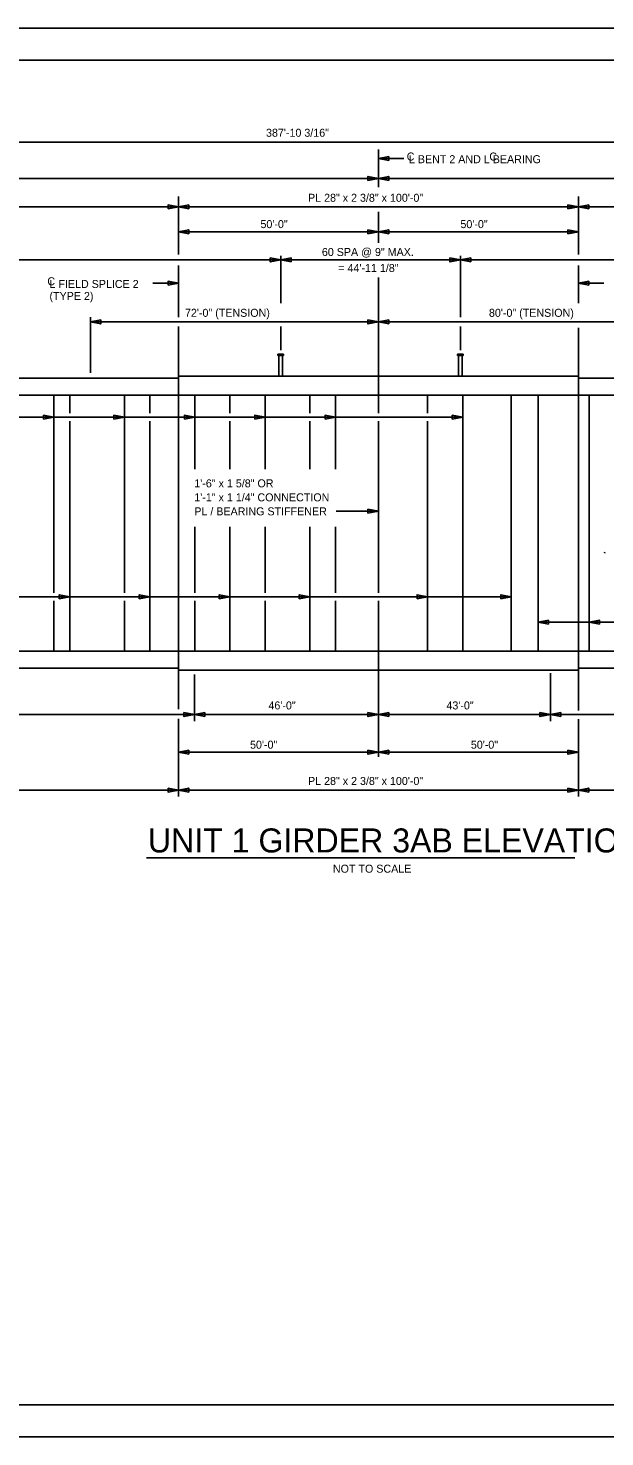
# Model space of a CAD drawing. Extents: x -305 to -161, y -187 to -99.
# Drawn here: x -251.9 to -215.9, y -187.5 to -99.5 of the extents above; entities that cross this region are included whole.
import ezdxf

# ---------------------------------------------------------------- set-up
doc = ezdxf.new("R2010")
doc.units = 0
for name, color, linetype in [('BR_AUTO DIMENSION', 7, 'Continuous'), ('BR_BORDER LINES', 7, 'Continuous'), ('BR_CENTER LINES', 7, 'Continuous'), ('BR_STRUCTURAL STEEL', 7, 'Continuous'), ('BR_TEXT', 7, 'Continuous'), ('Default', 7, 'Continuous'), ('Level 31', 7, 'Continuous')]:
    doc.layers.add(name, color=color, linetype=linetype)

msp = doc.modelspace()

# ---------------------------------------------------------------- linework, layer by layer
at = {"layer": 'BR_AUTO DIMENSION'}
for p, q in [((-284.516, -106.618), (-185.804, -106.618)), ((-230.055, -107.634), (-228.457, -107.634)), ((-284.516, -108.876), (-230.055, -108.876)), ((-230.055, -108.876), (-185.804, -108.876)), ((-242.555, -110.653), (-268.805, -110.653)), ((-242.555, -110.653), (-217.555, -110.653)), ((-217.555, -110.653), (-197.555, -110.653)), ((-230.055, -112.204), (-242.555, -112.204)), ((-217.555, -112.204), (-230.055, -112.204)), ((-282.849, -113.971), (-236.162, -113.971)), ((-236.162, -116.66), (-236.162, -113.721)), ((-236.162, -113.971), (-224.929, -113.971)), ((-224.929, -117.534), (-224.929, -113.721)), ((-224.929, -113.971), (-187.054, -113.971)), ((-242.555, -115.428), (-244.154, -115.428)), ((-217.555, -115.428), (-215.957, -115.428)), ((-248.055, -117.55), (-248.055, -121.025)), ((-248.055, -117.84), (-230.055, -117.84)), ((-210.055, -117.84), (-230.055, -117.84)), ((-236.162, -119.6), (-236.162, -118.13)), ((-224.929, -119.6), (-224.929, -118.13)), ((-224.787, -123.792), (-287.874, -123.792)), ((-230.055, -129.663), (-232.704, -129.663)), ((-221.751, -135.013), (-287.874, -135.013)), ((-220.077, -136.601), (-182.254, -136.601)), ((-241.555, -139.874), (-241.555, -142.773)), ((-219.305, -139.78), (-219.305, -142.773)), ((-241.555, -142.367), (-284.516, -142.367)), ((-230.055, -142.367), (-241.555, -142.367)), ((-219.305, -142.367), (-230.055, -142.367)), ((-185.804, -142.367), (-219.305, -142.367)), ((-230.055, -144.726), (-242.555, -144.726)), ((-217.555, -144.726), (-230.055, -144.726)), ((-268.805, -147.085), (-242.555, -147.085)), ((-242.555, -147.085), (-217.555, -147.085)), ((-217.555, -147.085), (-197.555, -147.085))]:
    msp.add_line(p, q, dxfattribs=at)
for points in [[(-229.405, -107.759), (-230.055, -107.634), (-229.405, -107.509)], [(-230.705, -109.001), (-230.055, -108.876), (-230.705, -108.751)], [(-229.405, -109.001), (-230.055, -108.876), (-229.405, -108.751)], [(-243.205, -110.778), (-242.555, -110.653), (-243.205, -110.528)], [(-241.905, -110.778), (-242.555, -110.653), (-241.905, -110.528)], [(-218.205, -110.778), (-217.555, -110.653), (-218.205, -110.528)], [(-216.905, -110.778), (-217.555, -110.653), (-216.905, -110.528)], [(-241.905, -112.329), (-242.555, -112.204), (-241.905, -112.079)], [(-230.705, -112.079), (-230.055, -112.204), (-230.705, -112.329)], [(-229.405, -112.329), (-230.055, -112.204), (-229.405, -112.079)], [(-218.205, -112.079), (-217.555, -112.204), (-218.205, -112.329)], [(-236.812, -113.846), (-236.162, -113.971), (-236.812, -114.096)], [(-235.512, -114.096), (-236.162, -113.971), (-235.512, -113.846)], [(-225.579, -113.846), (-224.929, -113.971), (-225.579, -114.096)], [(-224.279, -114.096), (-224.929, -113.971), (-224.279, -113.846)], [(-243.205, -115.553), (-242.555, -115.428), (-243.205, -115.303)], [(-216.905, -115.553), (-217.555, -115.428), (-216.905, -115.303)], [(-247.405, -117.715), (-248.055, -117.84), (-247.405, -117.965)], [(-230.705, -117.715), (-230.055, -117.84), (-230.705, -117.965)], [(-229.405, -117.965), (-230.055, -117.84), (-229.405, -117.715)], [(-250.982, -123.917), (-250.332, -123.792), (-250.982, -123.667)], [(-246.582, -123.917), (-245.932, -123.792), (-246.582, -123.667)], [(-242.182, -123.917), (-241.532, -123.792), (-242.182, -123.667)], [(-237.782, -123.917), (-237.132, -123.792), (-237.782, -123.667)], [(-233.382, -123.917), (-232.732, -123.792), (-233.382, -123.667)], [(-225.437, -123.917), (-224.787, -123.792), (-225.437, -123.667)], [(-230.705, -129.788), (-230.055, -129.663), (-230.705, -129.538)], [(-249.999, -135.138), (-249.349, -135.013), (-249.999, -134.888)], [(-244.999, -135.138), (-244.349, -135.013), (-244.999, -134.888)], [(-239.999, -135.138), (-239.349, -135.013), (-239.999, -134.888)], [(-234.999, -135.138), (-234.349, -135.013), (-234.999, -134.888)], [(-227.639, -135.138), (-226.989, -135.013), (-227.639, -134.888)], [(-222.401, -135.138), (-221.751, -135.013), (-222.401, -134.888)], [(-219.427, -136.726), (-220.077, -136.601), (-219.427, -136.476)], [(-216.232, -136.726), (-216.882, -136.601), (-216.232, -136.476)], [(-242.205, -142.242), (-241.555, -142.367), (-242.205, -142.492)], [(-240.905, -142.492), (-241.555, -142.367), (-240.905, -142.242)], [(-230.705, -142.242), (-230.055, -142.367), (-230.705, -142.492)], [(-229.405, -142.492), (-230.055, -142.367), (-229.405, -142.242)], [(-219.955, -142.242), (-219.305, -142.367), (-219.955, -142.492)], [(-218.655, -142.492), (-219.305, -142.367), (-218.655, -142.242)], [(-241.905, -144.851), (-242.555, -144.726), (-241.905, -144.601)], [(-230.705, -144.601), (-230.055, -144.726), (-230.705, -144.851)], [(-229.405, -144.851), (-230.055, -144.726), (-229.405, -144.601)], [(-218.205, -144.601), (-217.555, -144.726), (-218.205, -144.851)], [(-243.205, -146.96), (-242.555, -147.085), (-243.205, -147.21)], [(-241.905, -147.21), (-242.555, -147.085), (-241.905, -146.96)], [(-218.205, -146.96), (-217.555, -147.085), (-218.205, -147.21)], [(-216.905, -147.21), (-217.555, -147.085), (-216.905, -146.96)]]:
    msp.add_lwpolyline(points, close=True, dxfattribs=at)
at = {"layer": 'BR_BORDER LINES'}
for p, q in [((-163.178, -101.489), (-297.843, -101.489)), ((-297.843, -185.489), (-163.178, -185.489))]:
    msp.add_line(p, q, dxfattribs=at)
at = {"layer": 'BR_CENTER LINES'}
for p, q in [((-230.055, -107.059), (-230.055, -109.43)), ((-242.555, -109.997), (-242.555, -113.625)), ((-217.555, -109.997), (-217.555, -113.625)), ((-230.055, -110.967), (-230.055, -112.893)), ((-242.555, -114.323), (-242.555, -117.534)), ((-217.555, -114.323), (-217.555, -116.659)), ((-230.055, -115.073), (-230.055, -122.412)), ((-242.555, -118.13), (-242.555, -124.614)), ((-217.555, -118.212), (-217.555, -126.919)), ((-242.555, -124.614), (-242.555, -142.034)), ((-217.555, -126.919), (-217.555, -142.11)), ((-230.055, -138.412), (-230.055, -145.014)), ((-242.555, -142.631), (-242.555, -147.486)), ((-217.555, -142.664), (-217.555, -147.486))]:
    msp.add_line(p, q, dxfattribs=at)
at = {"layer": 'BR_STRUCTURAL STEEL'}
for p, q in [((-268.805, -121.35), (-242.555, -121.35)), ((-242.555, -122.412), (-242.555, -121.225)), ((-242.555, -121.225), (-217.555, -121.225)), ((-217.555, -121.225), (-217.555, -122.412)), ((-217.555, -121.35), (-197.555, -121.35)), ((-185.804, -122.412), (-284.516, -122.412)), ((-250.332, -122.412), (-250.332, -134.771)), ((-249.349, -122.412), (-249.349, -123.55)), ((-245.932, -122.412), (-245.932, -134.771)), ((-244.349, -122.412), (-244.349, -123.55)), ((-241.532, -122.412), (-241.532, -127.034)), ((-239.349, -122.412), (-239.349, -123.55)), ((-237.132, -122.412), (-237.132, -127.034)), ((-234.349, -122.412), (-234.349, -123.55)), ((-232.732, -122.412), (-232.732, -127.034)), ((-230.055, -122.412), (-230.055, -123.55)), ((-226.989, -123.55), (-226.989, -122.412)), ((-224.787, -138.412), (-224.787, -122.412)), ((-221.751, -138.412), (-221.751, -122.412)), ((-220.077, -138.412), (-220.077, -122.412)), ((-216.882, -138.412), (-216.882, -122.412)), ((-249.349, -124.034), (-249.349, -138.412)), ((-244.349, -124.034), (-244.349, -138.412)), ((-239.349, -124.034), (-239.349, -127.034)), ((-234.349, -124.034), (-234.349, -127.034)), ((-230.055, -124.034), (-230.055, -134.771)), ((-226.989, -138.412), (-226.989, -124.034)), ((-241.532, -130.636), (-241.532, -134.771)), ((-239.349, -130.636), (-239.349, -138.412)), ((-237.132, -130.636), (-237.132, -134.771)), ((-234.349, -130.636), (-234.349, -138.412)), ((-232.732, -130.636), (-232.732, -134.771)), ((-250.332, -135.255), (-250.332, -138.412)), ((-245.932, -135.255), (-245.932, -138.412)), ((-241.532, -135.255), (-241.532, -138.412)), ((-237.132, -135.255), (-237.132, -138.412)), ((-232.732, -135.255), (-232.732, -138.412)), ((-230.055, -135.255), (-230.055, -138.412)), ((-185.804, -138.412), (-284.516, -138.412)), ((-242.555, -138.412), (-242.555, -139.6)), ((-217.555, -139.6), (-217.555, -138.412)), ((-268.805, -139.475), (-242.555, -139.475)), ((-242.555, -139.6), (-217.555, -139.6)), ((-217.555, -139.475), (-197.555, -139.475))]:
    msp.add_line(p, q, dxfattribs=at)
at = {"layer": 'BR_TEXT'}
for p, q in [((-215.931, -132.279), (-215.901, -132.233)), ((-244.54, -151.32), (-217.77, -151.32))]:
    msp.add_line(p, q, dxfattribs=at)
at = {"layer": 'Default'}
for p, q in [((-236.334, -119.85), (-236.334, -119.944)), ((-236.334, -119.85), (-235.99, -119.85)), ((-236.334, -119.944), (-235.99, -119.944)), ((-236.271, -119.944), (-236.271, -121.225)), ((-236.052, -119.944), (-236.052, -121.225)), ((-235.99, -119.85), (-235.99, -119.944)), ((-225.101, -119.85), (-225.101, -119.944)), ((-225.101, -119.85), (-224.758, -119.85)), ((-225.101, -119.944), (-224.758, -119.944)), ((-225.039, -119.944), (-225.039, -121.225)), ((-224.82, -119.944), (-224.82, -121.225)), ((-224.758, -119.85), (-224.758, -119.944))]:
    msp.add_line(p, q, dxfattribs=at)
at = {"layer": 'Level 31'}
msp.add_lwpolyline([(-305.176, -187.489), (-161.176, -187.489), (-161.176, -99.489), (-305.176, -99.489)], close=True, dxfattribs=at)

# ---------------------------------------------------------------- texts
at = {"layer": 'BR_AUTO DIMENSION'}
for s, p in [('387\'-10 3/16"', (-237.078, -106.272)), ('PL 28" x 2 3/8" x 100\'-0"', (-234.452, -110.334)), ('50\'-0"', (-237.427, -111.979)), ('50\'-0"', (-224.927, -111.979)), (' 80\'-0" (TENSION)', (-223.329, -117.521)), ('46\'-0"', (-236.927, -142.048)), ('50\'-0"', (-238.077, -144.501)), ('50\'-0"', (-224.276, -144.501)), ('PL 28" x 2 3/8" x 100\'-0"', (-234.452, -146.766))]:
    msp.add_text(s, height=0.5, rotation=360, dxfattribs=at).set_placement(p)
for s, p in [('60 SPA @ 9" MAX.', (-233.587, -113.721)), ('= 44\'-11 1/8"', (-232.561, -114.721)), (' 72\'-0" (TENSION)', (-242.329, -117.521)), ('43\'-0"', (-225.802, -142.048))]:
    msp.add_text(s, height=0.5, dxfattribs=at).set_placement(p)
at = {"layer": 'BR_TEXT'}
for s, p in [('C', (-228.282, -107.758)), ('C', (-223.123, -107.758)), ('L BENT 2 AND L BEARING', (-228.147, -107.924)), ('C', (-250.748, -115.551)), ('L FIELD SPLICE 2', (-250.613, -115.718)), ('(TYPE 2)', (-250.613, -116.468)), ('1\'-6" x 1 5/8" OR', (-241.561, -128.174)), ('1\'-1" x 1 1/4" CONNECTION ', (-241.561, -129.049)), ('PL / BEARING STIFFENER', (-241.561, -129.924))]:
    msp.add_text(s, height=0.5, rotation=360, dxfattribs=at).set_placement(p)
for s, height, p in [('UNIT 1 GIRDER 3AB ELEVATION', 1.5, (-244.46, -150.983)), ('NOT TO SCALE', 0.5, (-232.898, -152.247))]:
    msp.add_text(s, height=height, dxfattribs=at).set_placement(p)

doc.saveas('drawing.dxf')
